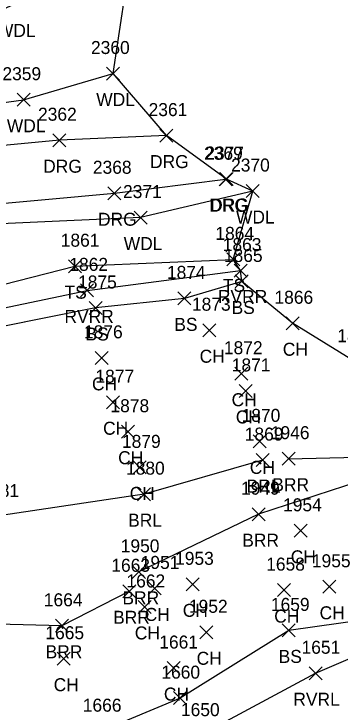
# Model space of a CAD drawing. Extents: x 1616726 to 1619875, y 273782 to 276557.
# Drawn here: x 1617094.9 to 1617145, y 276265.9 to 276373.3 of the extents above; entities that cross this region are included whole.
import ezdxf

# ---------------------------------------------------------------- set-up
doc = ezdxf.new("R2010")
doc.units = 0
for name, color, linetype in [('L_A', 7, 'Continuous'), ('L_I', 7, 'Continuous'), ('L_TIC', 7, 'Continuous'), ('LABL', 7, 'Continuous'), ('LAWA', 7, 'Continuous'), ('LAWE', 7, 'Continuous'), ('LELB', 7, 'Continuous'), ('LSOGP', 7, 'Continuous'), ('R_A', 7, 'Continuous'), ('R_I', 7, 'Continuous'), ('R_TIC', 7, 'Continuous'), ('RDG', 7, 'Continuous')]:
    doc.layers.add(name, color=color, linetype=linetype)

msp = doc.modelspace()

# ---------------------------------------------------------------- linework, layer by layer
at = {"layer": 'L_TIC'}
for points in [[(1617109.12, 276363.12), (1617111.12, 276365.12)], [(1617111.12, 276363.12), (1617109.12, 276365.12)], [(1617095.37, 276359.09), (1617097.37, 276361.09)], [(1617097.37, 276359.09), (1617095.37, 276361.09)], [(1617130.58, 276345.04), (1617132.58, 276347.04)], [(1617132.58, 276345.04), (1617130.58, 276347.04)], [(1617113.34, 276340.96), (1617115.34, 276342.96)], [(1617115.34, 276340.96), (1617113.34, 276342.96)], [(1617127.57, 276334.53), (1617129.57, 276336.53)], [(1617129.57, 276334.53), (1617127.57, 276336.53)], [(1617103.24, 276333.48), (1617105.24, 276335.48)], [(1617105.24, 276333.48), (1617103.24, 276335.48)], [(1617128.7, 276332.81), (1617130.7, 276334.81)], [(1617130.7, 276332.81), (1617128.7, 276334.81)], [(1617128.88, 276331.13), (1617130.88, 276333.13)], [(1617130.88, 276331.13), (1617128.88, 276333.13)], [(1617105.13, 276329.76), (1617107.13, 276331.76)], [(1617107.13, 276329.76), (1617105.13, 276331.76)], [(1617120.08, 276328.53), (1617122.08, 276330.53)], [(1617122.08, 276328.53), (1617120.08, 276330.53)], [(1617106.42, 276327.05), (1617108.42, 276329.05)], [(1617108.42, 276327.05), (1617106.42, 276329.05)], [(1617136.7, 276324.7), (1617138.7, 276326.7)], [(1617138.7, 276324.7), (1617136.7, 276326.7)], [(1617123.92, 276323.63), (1617125.92, 276325.63)], [(1617125.92, 276323.63), (1617123.92, 276325.63)], [(1617107.38, 276319.38), (1617109.38, 276321.38)], [(1617109.38, 276319.38), (1617107.38, 276321.38)], [(1617128.83, 276316.94), (1617130.83, 276318.94)], [(1617130.83, 276316.94), (1617128.83, 276318.94)], [(1617129.48, 276314.29), (1617131.48, 276316.29)], [(1617131.48, 276314.29), (1617129.48, 276316.29)], [(1617109.1, 276312.55), (1617111.1, 276314.55)], [(1617111.1, 276312.55), (1617109.1, 276314.55)], [(1617111.4, 276308.02), (1617113.4, 276310.02)], [(1617113.4, 276308.02), (1617111.4, 276310.02)], [(1617131.63, 276306.53), (1617133.63, 276308.53)], [(1617133.63, 276306.53), (1617131.63, 276308.53)], [(1617132.09, 276303.65), (1617134.09, 276305.65)], [(1617134.09, 276303.65), (1617132.09, 276305.65)], [(1617136.09, 276303.87), (1617138.09, 276305.87)], [(1617138.09, 276303.87), (1617136.09, 276305.87)], [(1617113.18, 276302.53), (1617115.18, 276304.53)], [(1617115.18, 276302.53), (1617113.18, 276304.53)], [(1617113.88, 276298.41), (1617115.88, 276300.41)], [(1617115.88, 276298.41), (1617113.88, 276300.41)], [(1617131.47, 276295.33), (1617133.47, 276297.33)], [(1617133.47, 276295.33), (1617131.47, 276297.33)], [(1617137.92, 276292.77), (1617139.92, 276294.77)], [(1617139.92, 276292.77), (1617137.92, 276294.77)], [(1617113.07, 276286.46), (1617115.07, 276288.46)], [(1617115.07, 276286.46), (1617113.07, 276288.46)], [(1617121.33, 276284.54), (1617123.33, 276286.54)], [(1617123.33, 276284.54), (1617121.33, 276286.54)], [(1617111.63, 276283.47), (1617113.63, 276285.47)], [(1617113.63, 276283.47), (1617111.63, 276285.47)], [(1617115.48, 276283.91), (1617117.48, 276285.91)], [(1617117.48, 276283.91), (1617115.48, 276285.91)], [(1617135.38, 276283.65), (1617137.38, 276285.65)], [(1617137.38, 276283.65), (1617135.38, 276285.65)], [(1617142.35, 276284.16), (1617144.35, 276286.16)], [(1617144.35, 276284.16), (1617142.35, 276286.16)], [(1617113.96, 276281.06), (1617115.96, 276283.06)], [(1617115.96, 276281.06), (1617113.96, 276283.06)], [(1617101.26, 276278.16), (1617103.26, 276280.16)], [(1617103.26, 276278.16), (1617101.26, 276280.16)], [(1617123.46, 276277.16), (1617125.46, 276279.16)], [(1617125.46, 276277.16), (1617123.46, 276279.16)], [(1617136.1, 276277.45), (1617138.1, 276279.45)], [(1617138.1, 276277.45), (1617136.1, 276279.45)], [(1617101.5, 276273.1), (1617103.5, 276275.1)], [(1617103.5, 276273.1), (1617101.5, 276275.1)], [(1617118.43, 276271.66), (1617120.43, 276273.66)], [(1617120.43, 276271.66), (1617118.43, 276273.66)], [(1617140.24, 276270.86), (1617142.24, 276272.86)], [(1617142.24, 276270.86), (1617140.24, 276272.86)], [(1617119.41, 276267.03), (1617121.41, 276269.03)], [(1617121.41, 276267.03), (1617119.41, 276269.03)]]:
    msp.add_lwpolyline(points, dxfattribs=at)
at = {"layer": 'LABL'}
for points in [[(1617133.09, 276304.65), (1617114.88, 276299.41), (1617091.86, 276295.96), (1617079.6, 276291.11), (1617061.1, 276287.27), (1617051.82, 276284.91)], [(1617137.09, 276304.87), (1617147.68, 276305.08), (1617147.85, 276301.38), (1617132.47, 276296.33), (1617114.07, 276287.46)], [(1617112.63, 276284.47), (1617102.26, 276279.16), (1617084.3, 276279.64), (1617073.52, 276281.41), (1617053.03, 276277.14), (1617049.76, 276283.08)]]:
    msp.add_lwpolyline(points, dxfattribs=at)
at = {"layer": 'LAWA'}
for points in [[(1617113.04, 276383.54), (1617094.85, 276374.74), (1617079.6, 276367.83), (1617070.44, 276362.66), (1617053.82, 276363.27), (1617042.07, 276364.37), (1617044.44, 276357.58), (1617059.39, 276355.54), (1617069.32, 276357.16), (1617079.37, 276357.75), (1617096.37, 276360.09), (1617110.12, 276364.12)], [(1617131.58, 276346.04), (1617114.34, 276341.96), (1617075.85, 276340.23), (1617060.16, 276335.63), (1617053.06, 276332.65)]]:
    msp.add_lwpolyline(points, dxfattribs=at)
at = {"layer": 'LAWE'}
for points in [[(1616789.07, 276346.62), (1616813.73, 276340.23), (1616836.2, 276333.67), (1616856.33, 276327.47), (1616874.72, 276318.98), (1616895.4, 276309.26), (1616910.77, 276301.56), (1616920.92, 276300.83), (1616931.35, 276302.77), (1616941.57, 276299.74), (1616947.81, 276295.8), (1616953.39, 276297.47), (1616960.89, 276300.06), (1616975.49, 276304.63), (1616989.93, 276306.41), (1617005.69, 276306.57), (1617020.09, 276309.06), (1617036.57, 276315.22), (1617052.5, 276318.39), (1617064.66, 276321.24), (1617083.34, 276325.98), (1617106.13, 276330.76), (1617129.7, 276333.81)], [(1617090.5, 276248.88), (1617102.37, 276255.86), (1617123.37, 276262.26), (1617141.24, 276271.86), (1617161.15, 276280.42), (1617181.53, 276284.74)]]:
    msp.add_lwpolyline(points, dxfattribs=at)
at = {"layer": 'LELB'}
for points in [[(1617045.38, 276318.98), (1617062.56, 276324.57), (1617081.98, 276328.81), (1617104.24, 276334.48), (1617128.57, 276335.53)], [(1617129.88, 276332.13), (1617121.08, 276329.53), (1617107.42, 276328.05), (1617085.5, 276323.64), (1617070.75, 276320.54), (1617052.83, 276314.23), (1617038.58, 276309.47), (1617032.52, 276309.94), (1617021.41, 276306.24), (1617009.94, 276306.04), (1616997.43, 276304.85), (1616977.4, 276301.81), (1616963.96, 276298.07)], [(1617180.33, 276288.33), (1617161.43, 276281.85), (1617137.1, 276278.45), (1617120.41, 276268.03), (1617108.3, 276262.95), (1617094.24, 276258.02), (1617079.48, 276248.1), (1617068.22, 276247.78), (1617049.15, 276245.5), (1617035.06, 276240.81), (1617026.01, 276236.23), (1617014.97, 276241.9), (1616972.47, 276247.82), (1616960.61, 276245.77), (1616944.03, 276250.47), (1616920.65, 276257.27), (1616898.69, 276263.02), (1616845.5, 276278.09), (1616816.83, 276290.56), (1616792.38, 276296.23)]]:
    msp.add_lwpolyline(points, dxfattribs=at)
at = {"layer": 'LSOGP'}
msp.add_lwpolyline([(1617147.3, 276319.79), (1617137.7, 276325.7), (1617129.88, 276332.13), (1617129.7, 276333.81), (1617128.57, 276335.53), (1617131.58, 276346.04), (1617127.54, 276347.89), (1617118.3, 276354.57), (1617110.11, 276364.12), (1617113.03, 276383.54)], dxfattribs=at)
at = {"layer": 'R_TIC'}
for points in [[(1617117.31, 276353.57), (1617119.31, 276355.57)], [(1617119.31, 276353.57), (1617117.31, 276355.57)], [(1617100.88, 276352.86), (1617102.88, 276354.86)], [(1617102.88, 276352.86), (1617100.88, 276354.86)], [(1617126.4, 276346.85), (1617128.4, 276348.85)], [(1617128.4, 276346.85), (1617126.4, 276348.85)], [(1617126.54, 276346.89), (1617128.54, 276348.89)], [(1617128.54, 276346.89), (1617126.54, 276348.89)], [(1617109.31, 276344.7), (1617111.31, 276346.7)], [(1617111.31, 276344.7), (1617109.31, 276346.7)]]:
    msp.add_lwpolyline(points, dxfattribs=at)
at = {"layer": 'RDG'}
for points in [[(1617118.31, 276354.57), (1617101.88, 276353.86), (1617080.39, 276351.8), (1617066.61, 276351.52)], [(1617044.05, 276342.65), (1617062.79, 276342.21), (1617077.21, 276342.68), (1617110.31, 276345.7), (1617127.4, 276347.85), (1617127.54, 276347.89)]]:
    msp.add_lwpolyline(points, dxfattribs=at)

# ---------------------------------------------------------------- texts
at = {"layer": 'L_A'}
for s, p in [('WDL', (1617092.27, 276369.74)), ('WDL', (1617107.53, 276359.12)), ('WDL', (1617093.79, 276355.09)), ('WDL', (1617129, 276341.04)), ('WDL', (1617111.75, 276336.96)), ('TS', (1617126.98, 276330.53)), ('TS', (1617102.65, 276329.48)), ('RVRR', (1617126.22, 276328.81)), ('BS', (1617128.32, 276327.13)), ('RVRR', (1617102.64, 276325.76)), ('BS', (1617119.52, 276324.53)), ('BS', (1617105.86, 276323.05)), ('CH', (1617136.19, 276320.7)), ('CH', (1617123.41, 276319.63)), ('CH', (1617106.87, 276315.38)), ('CH', (1617128.32, 276312.94)), ('CH', (1617128.97, 276310.29)), ('CH', (1617108.58, 276308.55)), ('CH', (1617110.89, 276304.02)), ('CH', (1617131.12, 276302.53)), ('BRL', (1617130.64, 276299.65)), ('BRR', (1617134.58, 276299.87)), ('CH', (1617112.67, 276298.53)), ('BRL', (1617112.43, 276294.41)), ('BRR', (1617129.96, 276291.33)), ('CH', (1617137.41, 276288.77)), ('BRR', (1617111.55, 276282.46)), ('CH', (1617114.97, 276279.91)), ('CH', (1617120.82, 276280.54)), ('CH', (1617141.84, 276280.16)), ('BRR', (1617110.12, 276279.47)), ('CH', (1617134.87, 276279.65)), ('CH', (1617113.45, 276277.06)), ('BRR', (1617099.75, 276274.16)), ('BS', (1617135.55, 276273.45)), ('CH', (1617122.95, 276273.16)), ('CH', (1617100.99, 276269.1)), ('CH', (1617117.92, 276267.66)), ('RVRL', (1617137.81, 276266.86))]:
    msp.add_text(s, height=2, dxfattribs=at).set_placement(p)
at = {"layer": 'L_I'}
for s, p in [('2360', (1617106.72, 276367.12)), ('2359', (1617093.11, 276363.09)), ('2370', (1617128.24, 276349.04)), ('2371', (1617111.64, 276344.96)), ('1864', (1617125.83, 276338.53)), ('1861', (1617102.07, 276337.48)), ('1863', (1617126.96, 276336.81)), ('1865', (1617127.14, 276335.13)), ('1862', (1617103.39, 276333.76)), ('1874', (1617118.39, 276332.53)), ('1875', (1617104.73, 276331.05)), ('1866', (1617134.91, 276328.7)), ('1873', (1617122.23, 276327.63)), ('1876', (1617105.64, 276323.38)), ('1867', (1617144.56, 276322.79)), ('1872', (1617127.14, 276320.94)), ('1871', (1617128.35, 276318.29)), ('1877', (1617107.4, 276316.55)), ('1878', (1617109.71, 276312.02)), ('1870', (1617129.86, 276310.53)), ('1946', (1617134.35, 276307.87)), ('1869', (1617130.34, 276307.65)), ('1879', (1617111.48, 276306.53)), ('1880', (1617112.1, 276302.41)), ('1949', (1617129.77, 276299.33)), ('1881', (1617089.73, 276298.96)), ('1954', (1617136.23, 276296.77)), ('1950', (1617111.29, 276290.46)), ('1953', (1617119.64, 276288.54)), ('1663', (1617109.84, 276287.47)), ('1951', (1617114.36, 276287.91)), ('1658', (1617133.64, 276287.65)), ('1955', (1617140.66, 276288.16)), ('1662', (1617112.17, 276285.06)), ('1664', (1617099.47, 276282.16)), ('1952', (1617121.77, 276281.16)), ('1659', (1617134.36, 276281.45)), ('1665', (1617099.71, 276277.1)), ('1661', (1617117.21, 276275.66)), ('1651', (1617139.07, 276274.86)), ('1660', (1617117.53, 276271.03)), ('1666', (1617105.46, 276265.95)), ('1650', (1617120.54, 276265.26))]:
    msp.add_text(s, height=2, dxfattribs=at).set_placement(p)
at = {"layer": 'R_A'}
for p in [(1617099.37, 276348.86), (1617115.79, 276349.57), (1617124.89, 276342.85), (1617125.03, 276342.89), (1617107.8, 276340.7)]:
    msp.add_text('DRG', height=2, dxfattribs=at).set_placement(p)
at = {"layer": 'R_I'}
for s, p in [('2361', (1617115.57, 276357.57)), ('2362', (1617098.58, 276356.86)), ('2369', (1617124.09, 276350.85)), ('2377', (1617124.28, 276350.89)), ('2368', (1617107.01, 276348.7))]:
    msp.add_text(s, height=2, dxfattribs=at).set_placement(p)

doc.saveas('drawing.dxf')
